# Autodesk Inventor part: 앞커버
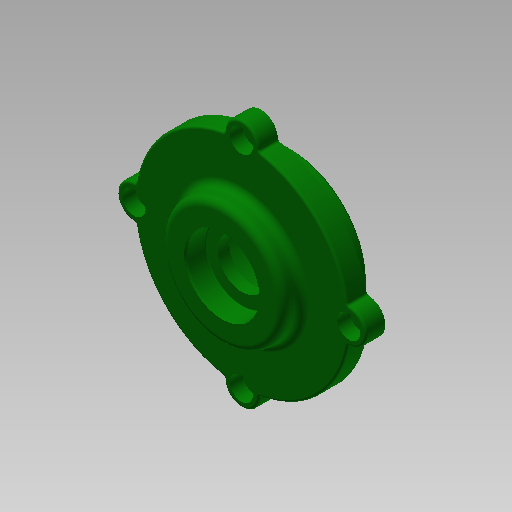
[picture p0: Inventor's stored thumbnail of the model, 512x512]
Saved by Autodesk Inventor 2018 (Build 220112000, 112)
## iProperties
Created: 2016-05
Part Number: 앞커버
Document SubType Name: Modeling
Designer: mduedu
Density: 2.71 g/cm^3
Material: 알루미늄 6061
Appearance: 진녹색
Author: mduedu
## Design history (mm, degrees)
sketch "스케치1"
  geometry: C1 r 32 at (0, 0); C2 r 44 at (0, 0); 1 further point
  constraints: 2 centre point, 2 coincident
  dimensions: "d33" = 88 diameter of C2; "d34" = 64 diameter of C1
extrude "돌출1" new body sketch "스케치1" distance "d0" = 8; taper "d1" = 0 deg
extrude "돌출2" join sketch "스케치1" distance "d2" = 8; taper "d3" = 0 deg; dims "d35" = 12, "d36" = 0
sketch "스케치6"
  geometry: C1 r 25 at (0, 0); 2 further points
  constraints: 2 coincident, 1 centre point
  dimensions: "d42" = 50 diameter of C1
extrude "돌출4" join sketch "스케치6" distance "d43" = 8; taper "d44" = 0 deg
sketch "스케치9"
  geometry: C1 r 7 at (0, 44); 2 further points
  constraints: 2 vertical alignment, 1 centre point, 1 other
  dimensions: "d70" = 14 diameter of C1
extrude "돌출5" join sketch "스케치9" stored distance "d71" = 10; taper "d72" = 0 deg
fillet "모깎기9" dims "d76" = 1
sketch "스케치10"
  geometry: C1 r 25 at (0, 0) reference; A1 r 1 centre (-44.284, 7.995) between (-44.249, 6.996) and (-43.3, 7.817) reference; A2 r 7 centre (-44, 0) between (-44.249, 6.996) and (-44.249, -6.996) reference; A3 r 1 centre (-44.284, -7.995) between (-43.3, -7.817) and (-44.249, -6.996) reference; A4 r 44 centre (0, 0) between (-43.3, -7.817) and (-7.817, -43.3) reference; A5 r 1 centre (-7.995, -44.284) between (-6.996, -44.249) and (-7.817, -43.3) reference; A6 r 7 centre (0, -44) between (-6.996, -44.249) and (6.996, -44.249) reference; A7 r 1 centre (7.995, -44.284) between (7.817, -43.3) and (6.996, -44.249) reference; A8 r 1 centre (7.995, 44.284) between (6.996, 44.249) and (7.817, 43.3) reference; A9 r 7 centre (0, 44) between (6.996, 44.249) and (-6.996, 44.249) reference; A10 r 1 centre (-7.995, 44.284) between (-7.817, 43.3) and (-6.996, 44.249) reference; A11 r 7 centre (44, 0) between (44.249, -6.996) and (44.249, 6.996) reference; A12 r 44 centre (0, 0) between (-7.817, 43.3) and (-43.3, 7.817) reference; A13 r 44 centre (0, 0) between (7.817, -43.3) and (43.3, -7.817) reference; A14 r 1 centre (44.284, -7.995) between (44.249, -6.996) and (43.3, -7.817) reference; A15 r 1 centre (44.284, 7.995) between (43.3, 7.817) and (44.249, 6.996) reference; A16 r 44 centre (0, 0) between (43.3, 7.817) and (7.817, 43.3) reference; 4 further points
  constraints: 3 coincident
hole "구멍3" sketch "스케치10" at (0, 44), (-44, 0), (0, -44), (44, 0) diameter "d77" = 5.5; stored, may be unused: countersink angle "d81" = 90 deg, drill point angle "d83" = 118 deg; dims "d78" = 6, "d79" = 9.5, "d80" = 5.4, "d82" = 8
fillet "모깎기10" dims "d84" = 1
fillet "모깎기7" dims "d68" = 3
fillet "모깎기8" dims "d69" = 3
sketch "스케치4"
  geometry: L1 (0, -12)-(0, 16); L2 (-20, -12)-(-20, 0); L3 (-20, 0)-(-15, 0); L4 (-15, 0)-(-15, 3); L5 (-15, 3)-(-10, 3); L6 (-10, 3)-(-10, 7.7); L7 (-10, 7.7)-(-15, 7.7); L8 (-15, 7.7)-(-15, 16); L9 (32, -12)-(-32, -12) reference; L10 (25, 16)-(-25, 16) reference; 1 further point
  constraints: 16 end point, 6 parallel, 3 point on line, 2 midpoint, 1 perpendicular, 1 vertical
  dimensions: "d15" = 40 diameter of L2 L1; "d16" = 30 diameter of L8 L1; "d18" = 12 distance of L2.start L2.end; "d19" = 3 distance of L3.end L4.end; "d20" = 30 diameter of L4 L1; "d21" = 20 diameter of L6 L1; "d45" = 8.3 distance of L7.end L8.end
revolve "회전1" sketch "스케치4" stored, may be unused: angle "d22" = 90 deg
fillet "모깎기2" dims "d23" = 3
fillet "모깎기3" dims "d24" = 0.3
chamfer "모따기2" distance "d46" = 1; stored, may be unused: second distance "d47" = 2, angle "d48" = 45 deg
chamfer "모따기3" distance "d64" = 0.8; stored, may be unused: second distance "d65" = 2, angle "d66" = 30 deg
node "솔리드1"
pattern_circular "원형 패턴1" dims angle "d74" = 360 deg
node "투영된 루프1"
